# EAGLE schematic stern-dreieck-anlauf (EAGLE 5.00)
12: 2; 21: 1; 72: 8; FUNKTION: Förderband; HERSTELLER: Siemens; NACH1: 222; NACH2: v22
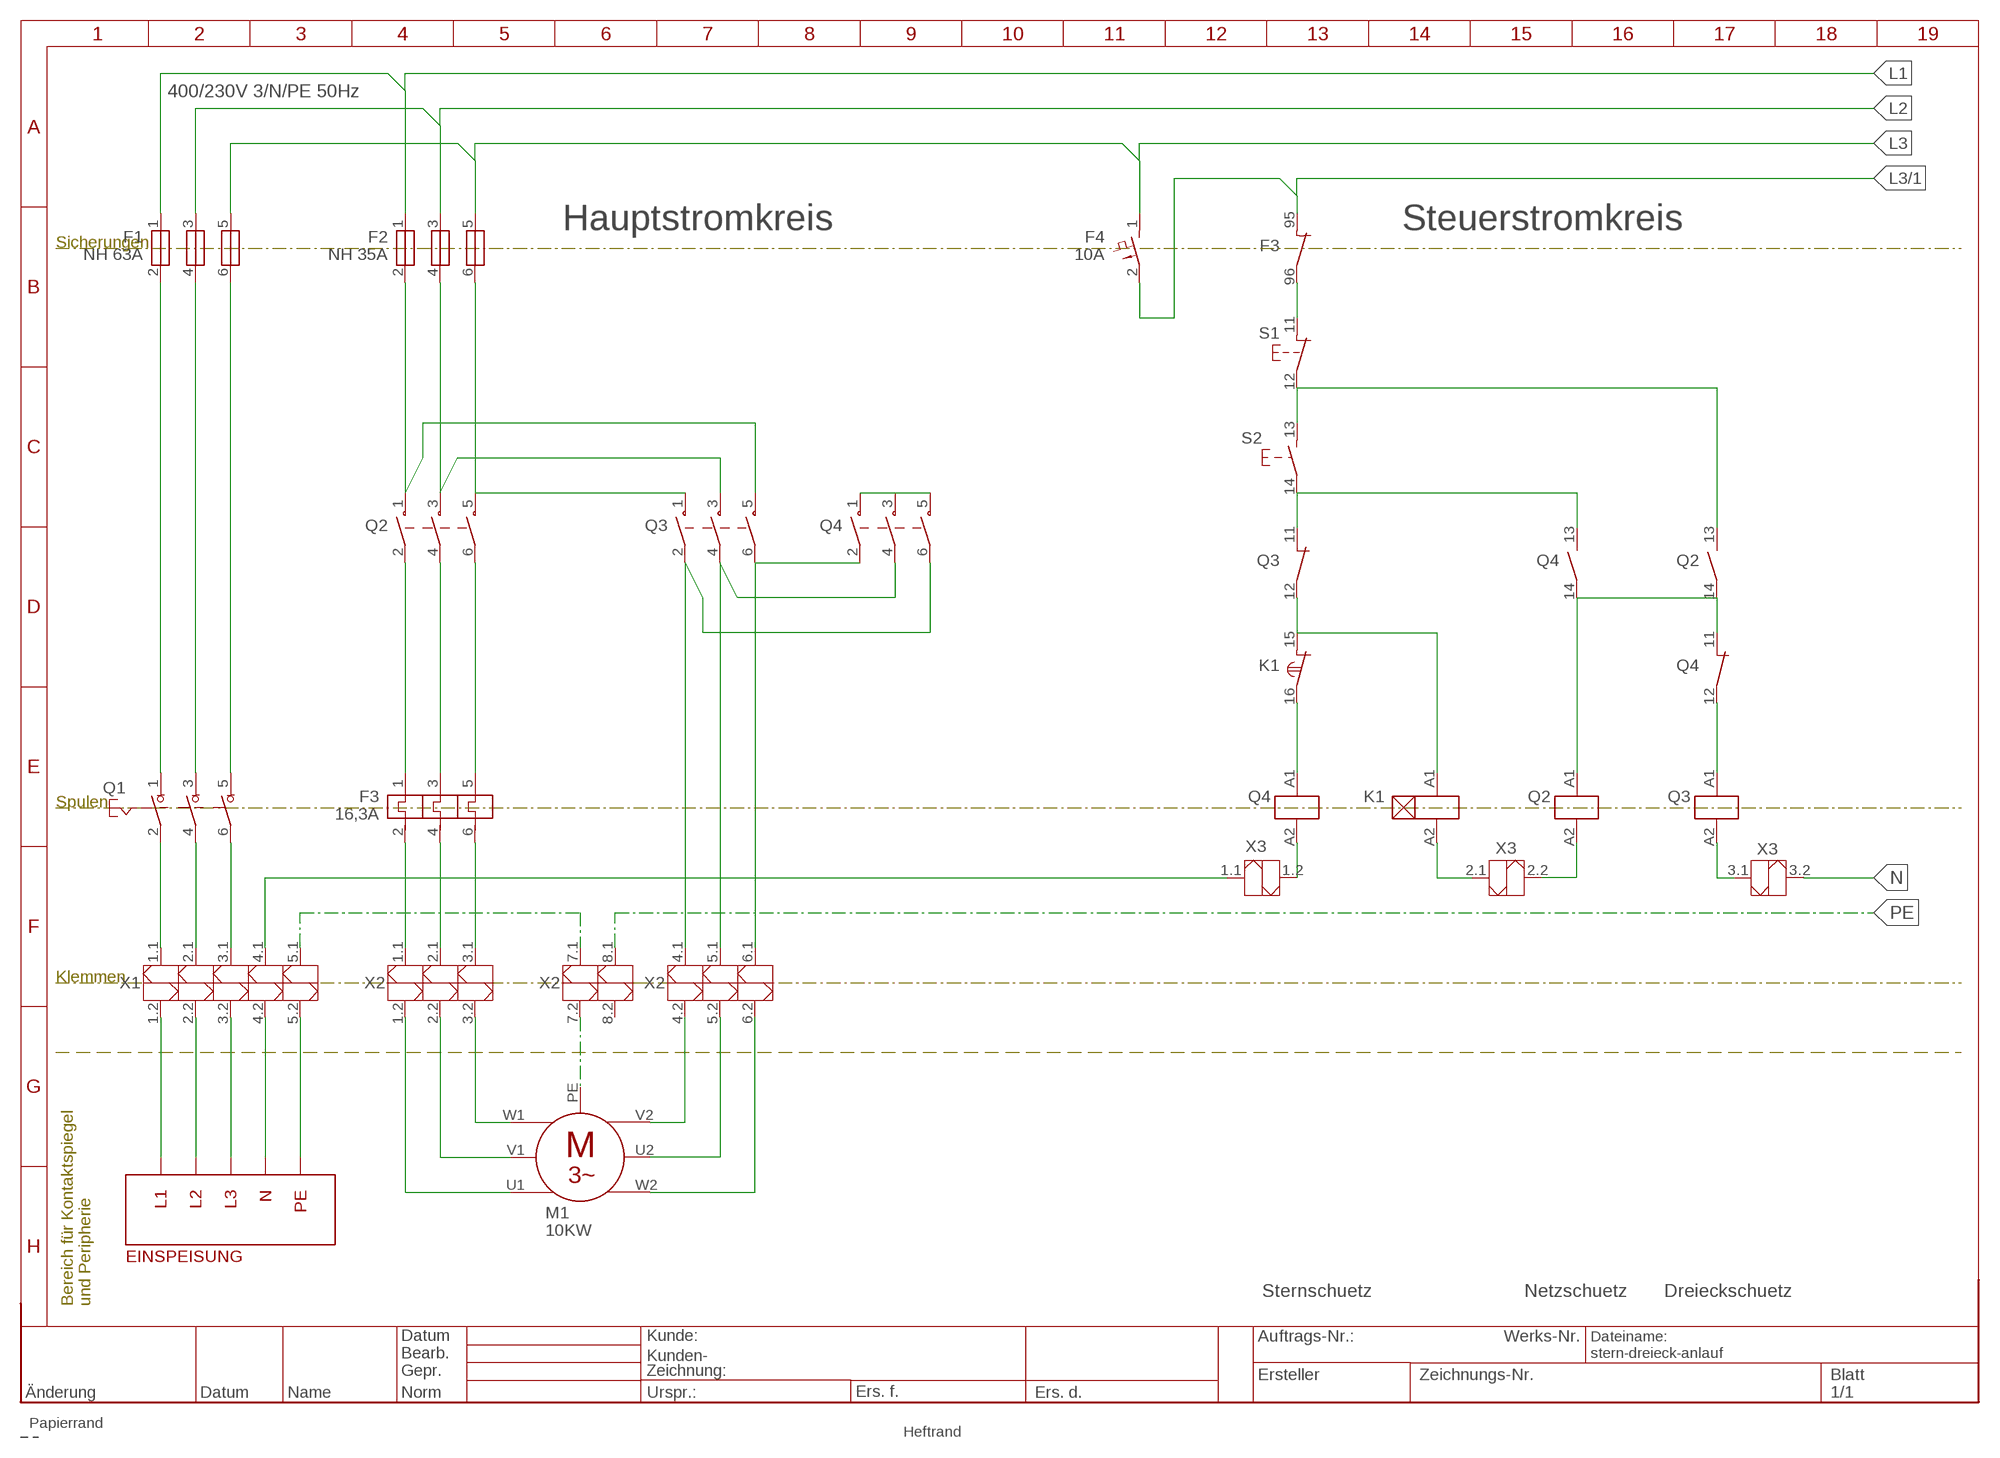
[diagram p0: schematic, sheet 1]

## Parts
F1  NH 63A  SICHERUNG_3-POL  [SICHERUNG_3-POL]
F2  NH 35A  SICHERUNG_3-POL  [SICHERUNG_3-POL]
F3  16,3A  MOTORSCHUTZSCHALTER_3-POL_THERM_AUSLOESUNG_HILFSKONTAKTE  [MOTORSCHUTZSCHALTER_3-POL_THERM_AUSLOESUNG_HILFSKONTAKT_95_96_97_98]
F4  10A  LEITUNGSSCHUTZSCHALTER  [LEITUNGSSCHUTZSCHALTER]
K1  HILFSSCHUETZ_OEFFNET_VERZOEGERT_15-16  [HILFSSCHUETZ_OEFFNET_VERZOEGERT_15-16]
M1  10KW  MOTOR_3-PHASEN_STERN-DREIECK-ANLAUF.ALTERNATIV  [MOTOR_3-PHASEN_STERN-DREIECK-ANLAUF.ALTERNATIV]
Q1  LASTTRENNSCHALTER_3-POL  [LASTTRENNSCHALTER_3-POL]
Q2  HAUPTSCHUETZ_3-POL_HILFSKONTAKT_13-14  [HAUPTSCHUETZ_3-POL+HILFSKONTAKT_13-14]
Q3  HAUPTSCHUETZ_3-POL_HILFSKONTAKT_11-12  [HAUPTSCHUETZ_3-POL+HILFSKONTAKT_11-12]
Q4  HAUPTSCHUETZ_3-POL_HILFSKONTAKT_11-12_13-14  [HAUPTSCHUETZ_3-POL+HILFSKONTAKT_12-12_13-14]
S1  TASTER_OEFFNER  [AUSTASTER]
S2  EINTASTER  [EINTASTER]
X1  KLEMME-2_6-BRUECKE  [KLEMME-2_6-BRUECKE]
X2  KLEMME-2_10-BRUECKE  [KLEMME-2_10-BRUECKE]
X3  KLEMME-2_6-BRUECKE  [KLEMME-2_6-BRUECKE]

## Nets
L1: F1.1 F2.1
L1-EXT: X1.1.2
L2: F1.3 F2.3
L2-EXT: X1.2.2
L3: F1.5 F2.5 F4.1
L3-EXT: X1.3.2
L3/1: F3.95 F4.2
N: X3.3.2
N$1: F1.2 Q1.1
N$2: Q3.11 Q4.13 S2.14(CS1)
N$3: F1.4 Q1.3
N$4: Q2.13 S1.12 S2.13(S1)
N$5: F1.6 Q1.5
N$6: F3.96 S1.11
N$7: F2.2 Q2.1 Q3.5
N$8: F3.1 Q2.2
N$9: M1.U1 X2.1.2
N$10: F2.4 Q2.3 Q3.3
N$11: F3.3 Q2.4
N$12: M1.V1 X2.2.2
N$13: F2.6 Q2.5 Q3.1
N$14: F3.5 Q2.6
N$15: M1.W1 X2.3.2
N$16: Q4.1 Q4.3 Q4.5
N$17: Q3.6 Q4.2 X2.6.1
N$18: Q3.4 Q4.4 X2.5.1
N$19: Q3.2 Q4.6 X2.4.1
N$20: K1.15 K1.A1 Q3.12
N$21: K1.16 Q4.A1
N$22: F3.2 X2.1.1
N$23: Q3.A1(1:A1) Q4.12
N$24: Q2.14 Q2.A1(1:A1) Q4.11 Q4.14
N$25: F3.4 X2.2.1
N$26: F3.6 X2.3.1
N$27: M1.V2 X2.4.2
N$28: M1.U2 X2.5.2
N$29: M1.W2 X2.6.2
N$30: Q1.2 X1.1.1
N$31: Q1.4 X1.2.1
N$32: Q1.6 X1.3.1
N$33: X1.4.1 X3.1.1
N$34: Q4.A2 X3.1.2
N$35: K1.A2 X3.2.1
N$36: Q2.A2(1:A2) X3.2.2
N$37: Q3.A2(1:A2) X3.3.1
N$39: X1.5.1 X2.7.1
N$40: M1.PE X2.7.2
N-EXT: X1.4.2
PE: X2.8.1
PE-EXT: X1.5.2
Unconnected: F3.97 F3.98 X1.6.1 X1.6.2 X2.8.2 X2.9.1 X2.9.2 X2.10.1 X2.10.2 X3.4.1 X3.4.2 X3.5.1 X3.5.2 X3.6.1 X3.6.2

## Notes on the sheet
- 400/230V 3/N/PE 50Hz
- Hauptstromkreis | Steuerstromkreis
- Sternschuetz | Netzschuetz | Dreieckschuetz

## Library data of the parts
F1 F2 = e-sicherungen:SICHERUNG_3-POL: Sicherung, 3-pol.
F3 = e-motorschutzschalter:MOTORSCHUTZSCHALTER_3-POL_THERM_AUSLOESUNG_HILFSKONTAKTE: Motorschutzschalter 3-pol. mit thermischer Auslösung, Hilfskontakte
F4 = e-sicherungen:LEITUNGSSCHUTZSCHALTER: Sicherung
K1 = e-schuetze-relais:HILFSSCHUETZ_OEFFNET_VERZOEGERT_15-16: Hilfsschütz mit Öffner, öffnet verzögert
M1 = e-motoren:MOTOR_3-PHASEN_STERN-DREIECK-ANLAUF.ALTERNATIV: 3-Phasen-Wechselstrom-Motor (alternativ)
Q1 = e-schalter:LASTTRENNSCHALTER_3-POL: Lasttrennschalter, 3-pol.
Q2 = e-schuetze-relais:HAUPTSCHUETZ_3-POL_HILFSKONTAKT_13-14: Hauptschütz 3-pol. mit Hilfskontakt-Schließer
Q3 = e-schuetze-relais:HAUPTSCHUETZ_3-POL_HILFSKONTAKT_11-12: Hauptschütz 3-pol. mit Hilfskontakt Öffner
Q4 = e-schuetze-relais:HAUPTSCHUETZ_3-POL_HILFSKONTAKT_11-12_13-14: Hauptschütz mit Öffner und Schließer
S1 = e-schalter:TASTER_OEFFNER: Austaster (Ruhekontakt)
S2 = e-schalter:EINTASTER: Ein-Taster (Arbeitskontakt)
X1 X3 = e-klemmen:KLEMME-2_6-BRUECKE: Klemme 6-pol. mit Brückenhinweis
X2 = e-klemmen:KLEMME-2_10-BRUECKE: Klemme 10-pol. mit Brückenhinweis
